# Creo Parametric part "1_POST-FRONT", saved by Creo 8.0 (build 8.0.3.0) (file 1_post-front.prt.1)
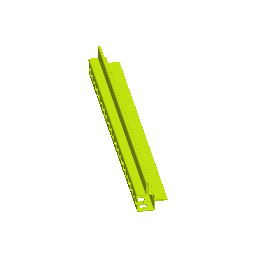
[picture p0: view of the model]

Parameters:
  SMT_DFLT_BEND_REL_LENGTH_TYPE = "Through All"

Other parameters: SMT_UPDATE_BEND_ALLOW_INFO, SMT_THICKNESS, SMT_PART_BEND_ALLOWANCE_FACTOR, SMT_DFLT_BEND_RADIUS, SMT_DFLT_BEND_ANGLE, SMT_DFLT_CRNR_REL_WIDTH, SMT_DFLT_CRNR_REL_DEPTH, SMT_DFLT_BEND_REL_WIDTH, SMT_DFLT_BEND_REL_DEPTH, SMT_DFLT_BEND_REL_LENGTH, SMT_DFLT_BEND_REL_ANGLE, SMT_GAP, SMT_DFLT_EDGE_TREA_WIDTH, SMT_DFLT_MITER_CUT_WIDTH, SMT_DFLT_MITER_CUT_OFFSET

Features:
  1. datum plane "RIGHT"
  2. datum plane "TOP"
  3. datum plane "FRONT"
  4. coordinate system
  5. pattern
  6. cut
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
Layers: 0_ALL_AXIS, 0_ALL_CSYS, 0_ALL_CURVES, 0_ALL_PLANES, 0_ALL_POINTS, 0_ALL_SURFS, POST-FRONT

Surfaces: 226 plane, 61 cylinder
